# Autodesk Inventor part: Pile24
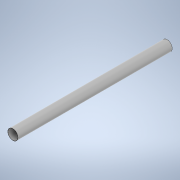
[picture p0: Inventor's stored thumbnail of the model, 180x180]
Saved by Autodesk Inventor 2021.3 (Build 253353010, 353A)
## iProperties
Created: 2021-11
Part Number: Pile24
Material: Steel, Mild
Document SubType Name: Modeling
Designer: u1426
Density: 7.85 g/cm^3
Appearance: Smooth - Medium Gray
Author: u1426
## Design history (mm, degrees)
sketch "Sketch1"
  geometry: C1 r 304.8 at (0, 0); C2 r 292.1 at (0, 0); 1 further point
  constraints: 2 centre point, 2 coincident
  dimensions: "d0" = 609.6 diameter of C1; "d1" = 12.7 radial gap between concentric circles of C2 C1
extrude "Extrusion1" new body sketch "Sketch1" distance "d2" = 9144; taper "d3" = 0 deg
body "Solid1"
